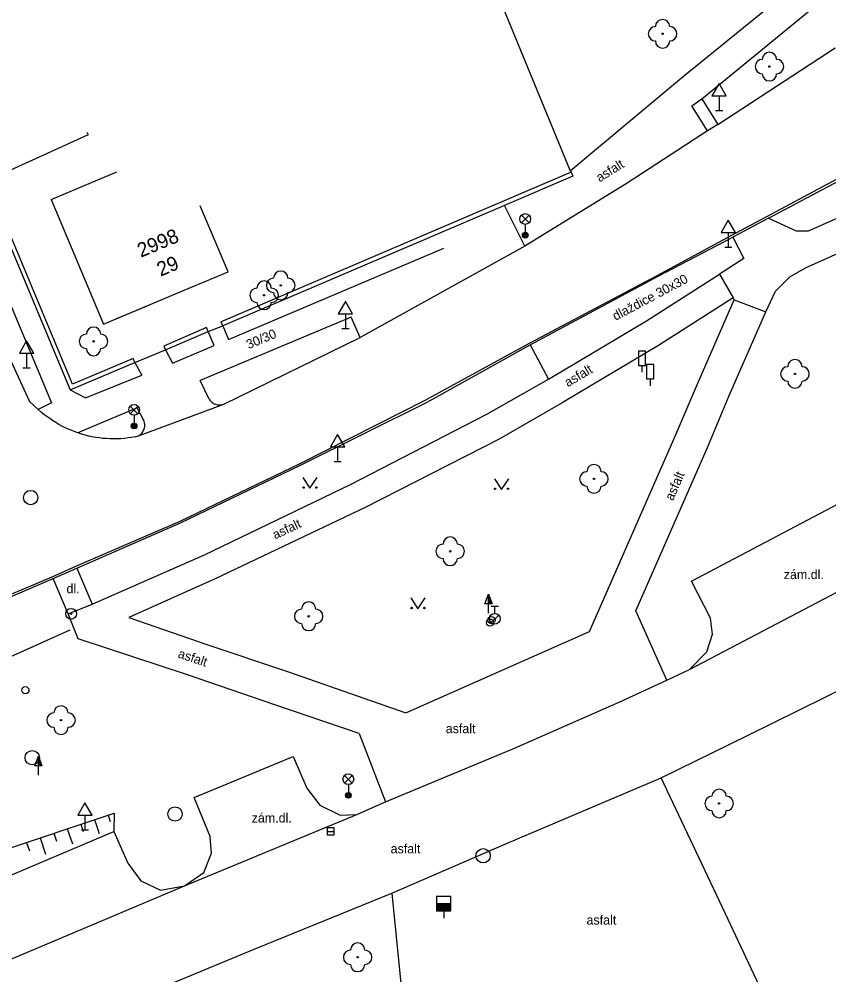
# Model space of a CAD drawing. Extents: x -539694 to -539148, y -1156467 to -1155920.
# Drawn here: x -539480.5 to -539424, y -1156055.6 to -1155988.9 of the extents above; entities that cross this region are included whole.
import ezdxf

# ---------------------------------------------------------------- set-up
doc = ezdxf.new("R2010")
doc.units = 0
for name, color, linetype in [('Vrstva 10', 7, 'Continuous'), ('Vrstva 11', 7, 'Continuous'), ('Vrstva 14', 7, 'Continuous'), ('Vrstva 15', 7, 'Continuous'), ('Vrstva 21', 7, 'Continuous'), ('Vrstva 22', 7, 'Continuous'), ('Vrstva 23', 7, 'Continuous'), ('Vrstva 25', 7, 'Continuous'), ('Vrstva 27', 7, 'Continuous'), ('Vrstva 28', 7, 'Continuous'), ('Vrstva 31', 7, 'Continuous'), ('Vrstva 33', 7, 'Continuous'), ('Vrstva 34', 7, 'Continuous'), ('Vrstva 36', 7, 'Continuous'), ('Vrstva 38', 7, 'Continuous'), ('Vrstva 40', 7, 'Continuous'), ('Vrstva 46', 7, 'Continuous'), ('Vrstva 47', 7, 'Continuous'), ('Vrstva 5', 7, 'Continuous'), ('Vrstva 6', 7, 'Continuous'), ('Vrstva 7', 7, 'Continuous'), ('Vrstva 8', 7, 'Continuous')]:
    doc.layers.add(name, color=color, linetype=linetype)

msp = doc.modelspace()

# ---------------------------------------------------------------- linework, layer by layer
at = {"layer": 'Vrstva 10'}
for p, q in [((-539488.78, -1155996.19), (-539479.82, -1156015.6)), ((-539466.257, -1156015.77), (-539456.736, -1156011.118)), ((-539479.22, -1156016.14), (-539479.82, -1156015.6)), ((-539472.218, -1156017.98), (-539466.257, -1156015.77))]:
    msp.add_line(p, q, dxfattribs=at)
msp.add_lwpolyline([(-539472.447, -1156018.059), (-539472.694, -1156018.102), (-539472.942, -1156018.137), (-539473.191, -1156018.165), (-539473.441, -1156018.184), (-539473.691, -1156018.195), (-539473.942, -1156018.199), (-539474.192, -1156018.194), (-539474.443, -1156018.181), (-539474.692, -1156018.161), (-539474.941, -1156018.132), (-539475.189, -1156018.095), (-539475.436, -1156018.051), (-539475.681, -1156017.999), (-539475.924, -1156017.939), (-539476.165, -1156017.871), (-539476.45, -1156017.78), (-539476.641, -1156017.712), (-539476.874, -1156017.622), (-539477.105, -1156017.524), (-539477.332, -1156017.418), (-539477.556, -1156017.306), (-539477.777, -1156017.186), (-539477.993, -1156017.06), (-539478.205, -1156016.926), (-539478.413, -1156016.786), (-539478.616, -1156016.64), (-539478.814, -1156016.487), (-539479.008, -1156016.327), (-539479.22, -1156016.14)], dxfattribs=at)
at = {"layer": 'Vrstva 11'}
for p, q in [((-539434.16, -1155992.88), (-539426.29, -1155986.46)), ((-539432.89, -1155994.46), (-539425.03, -1155988.02)), ((-539488.6, -1155991.01), (-539478.29, -1156015.69)), ((-539431.76, -1155996.24), (-539423.58, -1155990.88)), ((-539442.07, -1155999.47), (-539434.16, -1155992.88)), ((-539433.585, -1155994.939), (-539432.89, -1155994.46)), ((-539432.89, -1155994.46), (-539431.76, -1155996.24)), ((-539432.494, -1155996.698), (-539433.585, -1155994.939)), ((-539432.494, -1155996.698), (-539438.1, -1156000.33)), ((-539431.76, -1155996.24), (-539432.494, -1155996.698)), ((-539428.34, -1156002.67), (-539420.87, -1155998.67)), ((-539428.23, -1156002.79), (-539420.84, -1155998.85)), ((-539438.1, -1156000.33), (-539445.23, -1156004.73)), ((-539445.23, -1156004.73), (-539446.654, -1156001.901)), ((-539430.82, -1156003.99), (-539428.34, -1156002.67)), ((-539428.23, -1156002.79), (-539430.72, -1156004.12)), ((-539435.96, -1156006.76), (-539430.82, -1156003.99)), ((-539425.63, -1156006.25), (-539420.6, -1156004)), ((-539445.23, -1156004.73), (-539456.736, -1156011.118)), ((-539435.92, -1156006.83), (-539430.72, -1156004.12)), ((-539465.921, -1156011.252), (-539450.884, -1156004.879)), ((-539436.75, -1156009.96), (-539431.64, -1156006.69)), ((-539431.64, -1156006.69), (-539430.69, -1156008.36)), ((-539444.91, -1156011.52), (-539435.96, -1156006.76)), ((-539444.87, -1156011.62), (-539435.92, -1156006.83)), ((-539430.69, -1156008.36), (-539435.9, -1156011.67)), ((-539433.23, -1156014.48), (-539430.62, -1156008.5)), ((-539430.69, -1156008.36), (-539430.62, -1156008.5)), ((-539430.62, -1156008.5), (-539428.42, -1156009.33)), ((-539430.96, -1156015.17), (-539428.42, -1156009.33)), ((-539457.366, -1156009.693), (-539467.909, -1156014.119)), ((-539456.736, -1156011.118), (-539457.366, -1156009.693)), ((-539443.58, -1156014.04), (-539436.75, -1156009.96)), ((-539466.93, -1156011.68), (-539467.35, -1156010.7)), ((-539466.32, -1156010.31), (-539465.921, -1156011.252)), ((-539470.33, -1156011.99), (-539469.84, -1156012.92)), ((-539469.84, -1156012.92), (-539466.93, -1156011.68)), ((-539452.14, -1156015.47), (-539444.91, -1156011.52)), ((-539452.059, -1156015.631), (-539444.87, -1156011.62)), ((-539444.87, -1156011.62), (-539443.58, -1156014.04)), ((-539435.9, -1156011.67), (-539442.63, -1156015.69)), ((-539472.46, -1156012.86), (-539471.98, -1156013.74)), ((-539475.906, -1156015.333), (-539471.98, -1156013.74)), ((-539447.9, -1156016.47), (-539443.58, -1156014.04)), ((-539467.278, -1156015.416), (-539467.909, -1156014.119)), ((-539434.74, -1156018), (-539433.23, -1156014.48)), ((-539476.99, -1156014.78), (-539475.906, -1156015.333)), ((-539432.49, -1156018.79), (-539430.96, -1156015.17)), ((-539478.29, -1156015.69), (-539479.22, -1156016.14)), ((-539472.308, -1156016.021), (-539476.45, -1156017.78)), ((-539471.826, -1156016.973), (-539472.308, -1156016.021)), ((-539460.93, -1156019.91), (-539452.14, -1156015.47)), ((-539460.9, -1156020.03), (-539452.059, -1156015.631)), ((-539442.63, -1156015.69), (-539447.04, -1156018.23)), ((-539457.4, -1156021.39), (-539447.9, -1156016.47)), ((-539440.73, -1156031.65), (-539434.74, -1156018)), ((-539447.04, -1156018.23), (-539456.38, -1156023)), ((-539437.48, -1156030.21), (-539432.49, -1156018.79)), ((-539469.31, -1156023.95), (-539460.93, -1156019.91)), ((-539469.27, -1156024.06), (-539460.9, -1156020.03)), ((-539467.6, -1156026.3), (-539457.4, -1156021.39)), ((-539433.59, -1156028.13), (-539420.37, -1156021.15)), ((-539456.38, -1156023), (-539466.86, -1156027.97)), ((-539476.58, -1156027.09), (-539469.31, -1156023.95)), ((-539476.51, -1156027.22), (-539469.27, -1156024.06)), ((-539433.75, -1156034.31), (-539415.77, -1156024.85)), ((-539475.45, -1156029.73), (-539467.6, -1156026.3)), ((-539478.17, -1156027.94), (-539476.51, -1156027.22)), ((-539476.51, -1156027.22), (-539475.45, -1156029.73)), ((-539481.48, -1156029.36), (-539478.17, -1156027.94)), ((-539477.13, -1156030.42), (-539478.17, -1156027.94)), ((-539466.86, -1156027.97), (-539472.89, -1156030.67)), ((-539477.13, -1156030.42), (-539475.45, -1156029.73)), ((-539476.42, -1156032.16), (-539477.13, -1156030.42)), ((-539472.89, -1156030.67), (-539467.43, -1156032.55)), ((-539435.32, -1156035.05), (-539437.48, -1156030.21)), ((-539453.54, -1156037.33), (-539440.73, -1156031.65)), ((-539468.8, -1156034.68), (-539476.42, -1156032.16)), ((-539467.43, -1156032.55), (-539461.8, -1156034.45)), ((-539462.76, -1156036.74), (-539468.8, -1156034.68)), ((-539461.8, -1156034.45), (-539453.54, -1156037.33)), ((-539435.32, -1156035.05), (-539433.75, -1156034.31)), ((-539438.6, -1156036.56), (-539435.32, -1156035.05)), ((-539429.7, -1156038.92), (-539422.21, -1156035.22)), ((-539456.81, -1156038.77), (-539462.76, -1156036.74)), ((-539445.95, -1156039.79), (-539438.6, -1156036.56)), ((-539456.81, -1156038.77), (-539454.96, -1156043.54)), ((-539435.71, -1156041.86), (-539429.7, -1156038.92)), ((-539454.96, -1156043.54), (-539445.95, -1156039.79)), ((-539468.33, -1156043.24), (-539461.41, -1156040.37)), ((-539446.51, -1156046.45), (-539435.71, -1156041.86)), ((-539431.22, -1156051.37), (-539435.71, -1156041.86)), ((-539456.97, -1156044.43), (-539454.96, -1156043.54)), ((-539469, -1156049.41), (-539456.97, -1156044.43)), ((-539493.25, -1156053.83), (-539473.93, -1156045.61)), ((-539454.52, -1156049.93), (-539446.51, -1156046.45)), ((-539493.4, -1156059.73), (-539469, -1156049.41)), ((-539464.14, -1156053.84), (-539454.52, -1156049.93)), ((-539454.52, -1156049.93), (-539453.05, -1156064.8)), ((-539427.83, -1156058.57), (-539431.22, -1156051.37)), ((-539469.74, -1156056.16), (-539464.14, -1156053.84))]:
    msp.add_line(p, q, dxfattribs=at)
for points in [[(-539428.23, -1156002.79), (-539426.3, -1156003.68), (-539425.44, -1156003.68), (-539421.55, -1156001.95)], [(-539430.72, -1156004.12), (-539429.95, -1156005.6), (-539431.64, -1156006.69)], [(-539428.42, -1156009.33), (-539427.73, -1156007.88), (-539426.74, -1156006.88), (-539425.63, -1156006.25)], [(-539467.278, -1156015.416), (-539467.232, -1156015.484), (-539467.18, -1156015.548), (-539467.122, -1156015.606), (-539467.059, -1156015.658), (-539466.991, -1156015.704), (-539466.918, -1156015.743), (-539466.843, -1156015.774), (-539466.764, -1156015.798), (-539466.684, -1156015.815), (-539466.602, -1156015.823), (-539466.52, -1156015.824), (-539466.438, -1156015.816), (-539466.257, -1156015.77)], [(-539472.447, -1156018.059), (-539472.218, -1156017.98), (-539472.148, -1156017.939), (-539472.083, -1156017.891), (-539472.022, -1156017.837), (-539471.967, -1156017.778), (-539471.919, -1156017.713), (-539471.877, -1156017.644), (-539471.841, -1156017.571), (-539471.814, -1156017.495), (-539471.794, -1156017.416), (-539471.781, -1156017.336), (-539471.777, -1156017.255), (-539471.781, -1156017.174), (-539471.792, -1156017.094), (-539471.826, -1156016.973)], [(-539481.54, -1156029.23), (-539478.25, -1156027.84), (-539476.58, -1156027.09)], [(-539433.75, -1156034.31), (-539432.52, -1156033.06), (-539432.14, -1156031.84), (-539432.28, -1156030.72), (-539433.59, -1156028.13)], [(-539461.41, -1156040.37), (-539460.46, -1156042.58), (-539459.54, -1156043.77), (-539458.13, -1156044.47), (-539456.97, -1156044.43)], [(-539469, -1156049.41), (-539467.64, -1156048.47), (-539467.11, -1156047.12), (-539467.21, -1156045.97), (-539468.33, -1156043.24)], [(-539473.93, -1156045.61), (-539472.96, -1156047.82), (-539472.06, -1156049.07), (-539470.67, -1156049.72), (-539469, -1156049.41)]]:
    msp.add_lwpolyline(points, dxfattribs=at)
at = {"layer": 'Vrstva 14'}
for p, q in [((-539487.61, -1156048.92), (-539473.92, -1156044.33)), ((-539473.92, -1156044.33), (-539473.93, -1156045.61))]:
    msp.add_line(p, q, dxfattribs=at)
at = {"layer": 'Vrstva 15'}
for p, q in [((-539474.336, -1156044.47), (-539474.183, -1156044.928)), ((-539477.181, -1156045.423), (-539476.83, -1156046.47)), ((-539476.232, -1156045.105), (-539476.064, -1156045.607)), ((-539475.284, -1156044.787), (-539474.963, -1156045.747)), ((-539479.077, -1156046.059), (-539478.697, -1156047.192)), ((-539478.129, -1156045.741), (-539477.946, -1156046.286)), ((-539480.025, -1156046.377), (-539479.828, -1156046.965))]:
    msp.add_line(p, q, dxfattribs=at)
at = {"layer": 'Vrstva 21'}
for radius in [0.375, 0.05]:
    msp.add_circle((-539476.92, -1156030.41), radius, dxfattribs=at)
at = {"layer": 'Vrstva 22'}
for centre in [(-539435.62, -1155989.91), (-539428.16, -1155992.2), (-539462.28, -1156007.48), (-539463.44, -1156008.17), (-539475.35, -1156011.39), (-539426.38, -1156013.66), (-539440.41, -1156020.99), (-539450.45, -1156026.05), (-539460.33, -1156030.59), (-539477.62, -1156037.84), (-539431.67, -1156043.66), (-539456.91, -1156054.4)]:
    msp.add_circle(centre, 0.05, dxfattribs=at)
for centre, start, end in [((-539435.62, -1155989.41), 0, 180), ((-539436.12, -1155989.91), 90, 270), ((-539435.12, -1155989.91), 270, 90), ((-539435.62, -1155990.41), 180, 0), ((-539428.16, -1155991.7), 0, 180), ((-539428.66, -1155992.2), 90, 270), ((-539427.66, -1155992.2), 270, 90), ((-539428.16, -1155992.7), 180, 0), ((-539462.28, -1156006.98), 0, 180), ((-539463.44, -1156007.67), 0, 180), ((-539462.78, -1156007.48), 90, 270), ((-539461.78, -1156007.48), 270, 90), ((-539463.94, -1156008.17), 90, 270), ((-539462.94, -1156008.17), 270, 90), ((-539462.28, -1156007.98), 180, 0), ((-539463.44, -1156008.67), 180, 0), ((-539475.35, -1156010.89), 0, 180), ((-539475.85, -1156011.39), 90, 270), ((-539474.85, -1156011.39), 270, 90), ((-539475.35, -1156011.89), 180, 0), ((-539426.38, -1156013.16), 0, 180), ((-539426.88, -1156013.66), 90, 270), ((-539425.88, -1156013.66), 270, 90), ((-539426.38, -1156014.16), 180, 0), ((-539440.41, -1156020.49), 0, 180), ((-539440.91, -1156020.99), 90, 270), ((-539439.91, -1156020.99), 270, 90), ((-539440.41, -1156021.49), 180, 0), ((-539450.45, -1156025.55), 0, 180), ((-539450.95, -1156026.05), 90, 270), ((-539449.95, -1156026.05), 270, 90), ((-539450.45, -1156026.55), 180, 0), ((-539460.83, -1156030.59), 90, 270), ((-539460.33, -1156030.09), 0, 180), ((-539459.83, -1156030.59), 270, 90), ((-539460.33, -1156031.09), 180, 0), ((-539478.12, -1156037.84), 90, 270), ((-539477.62, -1156037.34), 0, 180), ((-539477.12, -1156037.84), 270, 90), ((-539477.62, -1156038.34), 180, 0), ((-539431.67, -1156043.16), 0, 180), ((-539432.17, -1156043.66), 90, 270), ((-539431.17, -1156043.66), 270, 90), ((-539431.67, -1156044.16), 180, 0), ((-539456.91, -1156053.9), 0, 180), ((-539457.41, -1156054.4), 90, 270), ((-539456.41, -1156054.4), 270, 90), ((-539456.91, -1156054.9), 180, 0)]:
    msp.add_arc(centre, 0.5, start, end, dxfattribs=at)
at = {"layer": 'Vrstva 23'}
msp.add_line((-539485.73, -1156035.47), (-539476.98, -1156031.53), dxfattribs=at)
at = {"layer": 'Vrstva 25'}
for p, q in [((-539479.453, -1156041.028), (-539479.2, -1156040.354)), ((-539479.2, -1156041.028), (-539479.453, -1156041.028)), ((-539479.2, -1156041.68), (-539479.2, -1156041.03))]:
    msp.add_line(p, q, dxfattribs=at)
for points in [[(-539478.95, -1156041.03), (-539479.2, -1156041.03), (-539479.2, -1156040.354), (-539479.2, -1156040.354)], [(-539479.008, -1156040.99), (-539479.161, -1156040.99), (-539479.161, -1156040.578)], [(-539479.065, -1156040.951), (-539479.121, -1156040.951), (-539479.121, -1156040.801)]]:
    msp.add_lwpolyline(points, close=True, dxfattribs=at)
at = {"layer": 'Vrstva 27'}
msp.add_line((-539459.04, -1156045.61), (-539458.54, -1156045.61), dxfattribs=at)
msp.add_lwpolyline([(-539459.04, -1156045.86), (-539458.54, -1156045.86), (-539458.54, -1156045.36), (-539459.04, -1156045.36)], close=True, dxfattribs=at)
for centre in [(-539479.74, -1156022.298), (-539479.63, -1156040.46), (-539469.663, -1156044.398), (-539448.15, -1156047.31)]:
    msp.add_circle(centre, 0.5, dxfattribs=at)
at = {"layer": 'Vrstva 28'}
for p, q in [((-539448.02, -1156029.708), (-539447.77, -1156029.034)), ((-539447.77, -1156029.708), (-539448.02, -1156029.708)), ((-539447.77, -1156030.36), (-539447.77, -1156029.71)), ((-539447.58, -1156029.884), (-539447.08, -1156029.884)), ((-539447.33, -1156030.384), (-539447.33, -1156029.884)), ((-539447.589, -1156031.031), (-539447.059, -1156030.501)), ((-539451.4, -1156050.65), (-539450.4, -1156050.65)), ((-539451.4, -1156050.701), (-539450.4, -1156050.701)), ((-539451.4, -1156050.751), (-539450.4, -1156050.751)), ((-539451.4, -1156050.8), (-539450.4, -1156050.8)), ((-539451.4, -1156050.851), (-539450.4, -1156050.851)), ((-539451.4, -1156050.9), (-539450.4, -1156050.9)), ((-539451.4, -1156050.951), (-539450.4, -1156050.951)), ((-539451.4, -1156051.001), (-539450.4, -1156051.001)), ((-539451.4, -1156051.05), (-539450.4, -1156051.05)), ((-539451.4, -1156051.101), (-539450.4, -1156051.101)), ((-539450.9, -1156051.15), (-539450.9, -1156051.68))]:
    msp.add_line(p, q, dxfattribs=at)
for points in [[(-539447.52, -1156029.71), (-539447.77, -1156029.71), (-539447.77, -1156029.034), (-539447.52, -1156029.71)], [(-539447.576, -1156029.669), (-539447.731, -1156029.669), (-539447.729, -1156029.257)], [(-539447.635, -1156029.63), (-539447.691, -1156029.63), (-539447.691, -1156029.48)], [(-539451.4, -1156051.15), (-539450.4, -1156051.15), (-539450.4, -1156050.15), (-539451.4, -1156050.15)]]:
    msp.add_lwpolyline(points, close=True, dxfattribs=at)
for centre, radius in [((-539447.57, -1156030.85), 0.25), ((-539447.33, -1156030.76), 0.375), ((-539447.67, -1156031.03), 0.25)]:
    msp.add_circle(centre, radius, dxfattribs=at)
at = {"layer": 'Vrstva 31'}
msp.add_circle((-539480.11, -1156035.75), 0.25, dxfattribs=at)
at = {"layer": 'Vrstva 33'}
for p, q in [((-539445.474, -1156003.111), (-539444.946, -1156002.581)), ((-539445.474, -1156002.581), (-539444.946, -1156003.111)), ((-539445.21, -1156003.22), (-539445.21, -1156003.97)), ((-539472.785, -1156016.44), (-539472.255, -1156015.91)), ((-539472.785, -1156015.91), (-539472.255, -1156016.44)), ((-539472.52, -1156016.55), (-539472.52, -1156017.3)), ((-539457.824, -1156042.231), (-539457.296, -1156041.701)), ((-539457.824, -1156041.701), (-539457.296, -1156042.231)), ((-539457.56, -1156042.34), (-539457.56, -1156043.09))]:
    msp.add_line(p, q, dxfattribs=at)
for centre, radius in [((-539445.21, -1156002.846), 0.375), ((-539445.21, -1156003.971), 0.2), ((-539445.21, -1156003.971), 0.145), ((-539445.21, -1156003.971), 0.0876), ((-539472.52, -1156016.175), 0.375), ((-539472.52, -1156017.3), 0.2), ((-539472.52, -1156017.3), 0.145), ((-539472.52, -1156017.3), 0.0876), ((-539457.56, -1156041.966), 0.375), ((-539457.56, -1156043.091), 0.2), ((-539457.56, -1156043.091), 0.145), ((-539457.56, -1156043.091), 0.0876)]:
    msp.add_circle(centre, radius, dxfattribs=at)
at = {"layer": 'Vrstva 34'}
for p, q in [((-539431.67, -1155994.254), (-539431.67, -1155995.27)), ((-539431.92, -1155995.27), (-539431.42, -1155995.27)), ((-539431.03, -1156003.784), (-539431.03, -1156004.8)), ((-539431.28, -1156004.8), (-539430.78, -1156004.8)), ((-539457.76, -1156009.472), (-539457.76, -1156010.49)), ((-539458.01, -1156010.49), (-539457.51, -1156010.49)), ((-539480.03, -1156012.212), (-539480.03, -1156013.23)), ((-539480.28, -1156013.23), (-539479.78, -1156013.23)), ((-539458.31, -1156018.764), (-539458.31, -1156019.78)), ((-539458.56, -1156019.78), (-539458.06, -1156019.78)), ((-539475.95, -1156044.474), (-539475.95, -1156045.49)), ((-539476.2, -1156045.49), (-539475.7, -1156045.49))]:
    msp.add_line(p, q, dxfattribs=at)
for points in [[(-539432.17, -1155994.254), (-539431.17, -1155994.254), (-539431.67, -1155993.386)], [(-539431.53, -1156003.784), (-539430.53, -1156003.784), (-539431.03, -1156002.916)], [(-539458.26, -1156009.472), (-539457.26, -1156009.472), (-539457.76, -1156008.606)], [(-539480.53, -1156012.212), (-539479.53, -1156012.212), (-539480.03, -1156011.346)], [(-539458.81, -1156018.764), (-539457.81, -1156018.764), (-539458.31, -1156017.896)], [(-539476.45, -1156044.474), (-539475.45, -1156044.474), (-539475.95, -1156043.606)]]:
    msp.add_lwpolyline(points, close=True, dxfattribs=at)
at = {"layer": 'Vrstva 36'}
for points in [[(-539460.74, -1156020.9), (-539460.24, -1156021.65), (-539459.74, -1156020.9)], [(-539447.36, -1156020.98), (-539446.86, -1156021.73), (-539446.36, -1156020.98)], [(-539453.2, -1156029.31), (-539452.7, -1156030.06), (-539452.2, -1156029.31)]]:
    msp.add_lwpolyline(points, dxfattribs=at)
for centre in [(-539460.69, -1156021.6), (-539459.791, -1156021.6), (-539447.31, -1156021.68), (-539446.411, -1156021.68), (-539453.15, -1156030.01), (-539452.251, -1156030.01)]:
    msp.add_circle(centre, 0.05, dxfattribs=at)
at = {"layer": 'Vrstva 38'}
for p, q in [((-539437.06, -1156013.066), (-539437.06, -1156013.55)), ((-539436.49, -1156014.006), (-539436.49, -1156014.49))]:
    msp.add_line(p, q, dxfattribs=at)
for points in [[(-539437.309, -1156013.066), (-539436.811, -1156013.066), (-539436.811, -1156012.065), (-539437.309, -1156012.065)], [(-539436.739, -1156014.006), (-539436.241, -1156014.006), (-539436.241, -1156013.005), (-539436.739, -1156013.005)]]:
    msp.add_lwpolyline(points, close=True, dxfattribs=at)
at = {"layer": 'Vrstva 5'}
for p, q in [((-539478.32, -1156001.49), (-539473.714, -1155999.545)), ((-539478.32, -1156001.49), (-539474.65, -1156010.18)), ((-539465.96, -1156006.53), (-539467.913, -1156001.927)), ((-539467.68, -1156007.26), (-539465.96, -1156006.53)), ((-539468.59, -1156007.62), (-539467.68, -1156007.26)), ((-539474.65, -1156010.18), (-539468.59, -1156007.62))]:
    msp.add_line(p, q, dxfattribs=at)
at = {"layer": 'Vrstva 6'}
for p, q in [((-539468.59, -1156007.62), (-539467.68, -1156007.26)), ((-539473.79, -1156009.81), (-539471.66, -1156008.93))]:
    msp.add_line(p, q, dxfattribs=at)
at = {"layer": 'Vrstva 7'}
for p, q in [((-539474.804, -1155920.039), (-539442.07, -1155999.47)), ((-539441.994, -1155999.583), (-539466.437, -1156010.034)), ((-539441.88, -1155999.86), (-539446.654, -1156001.901)), ((-539483.03, -1156000.29), (-539476.99, -1156014.78)), ((-539476.829, -1156014.386), (-539482.757, -1156000.166)), ((-539446.654, -1156001.901), (-539466.32, -1156010.31)), ((-539466.32, -1156010.31), (-539466.437, -1156010.034)), ((-539467.469, -1156010.425), (-539470.449, -1156011.715)), ((-539470.33, -1156011.99), (-539467.35, -1156010.7)), ((-539467.35, -1156010.7), (-539467.469, -1156010.425)), ((-539470.449, -1156011.715), (-539470.33, -1156011.99)), ((-539472.577, -1156012.584), (-539476.829, -1156014.386)), ((-539472.46, -1156012.86), (-539472.577, -1156012.584)), ((-539476.99, -1156014.78), (-539472.46, -1156012.86))]:
    msp.add_line(p, q, dxfattribs=at)
for points in [[(-539475.812, -1155996.787), (-539475.729, -1155996.969), (-539482.757, -1156000.166), (-539483.03, -1156000.29)], [(-539442.07, -1155999.47), (-539441.994, -1155999.583), (-539441.88, -1155999.86)]]:
    msp.add_lwpolyline(points, dxfattribs=at)
at = {"layer": 'Vrstva 8'}
for p, q in [((-539467.35, -1156010.7), (-539466.32, -1156010.31)), ((-539472.46, -1156012.86), (-539470.33, -1156011.99))]:
    msp.add_line(p, q, dxfattribs=at)

# ---------------------------------------------------------------- texts
at = {"layer": 'Vrstva 40'}
for s, rotation, p in [('asfalt', 32.17687, (-539440.006, -1156000.292)), ('dlaždice 30x30', 28.00602, (-539438.9, -1156009.96)), ('30/30', 22.77289, (-539464.521, -1156011.941)), ('asfalt', 30.85263, (-539442.23, -1156014.6)), ('asfalt', 66.49425, (-539434.897, -1156022.564)), ('asfalt', 25.37199, (-539462.67, -1156025.23)), ('asfalt', 341.70048, (-539469.51, -1156033.46))]:
    msp.add_text(s, height=0.65, rotation=rotation, dxfattribs=at).set_placement(p)
for s, p in [('zám.dl.', (-539427.16, -1156027.99)), ('dl.', (-539477.24, -1156028.98)), ('asfalt', (-539450.76, -1156038.75)), ('zám.dl.', (-539464.31, -1156044.99)), ('asfalt', (-539454.61, -1156047.14)), ('asfalt', (-539440.93, -1156052.12))]:
    msp.add_text(s, height=0.65, dxfattribs=at).set_placement(p)
at = {"layer": 'Vrstva 46'}
msp.add_text('29', height=1, rotation=23.10843, dxfattribs=at).set_placement((-539470.667, -1156006.874))
at = {"layer": 'Vrstva 47'}
msp.add_text('2998', height=1, rotation=22.78353, dxfattribs=at).set_placement((-539472.04, -1156005.55))

doc.saveas('drawing.dxf')
